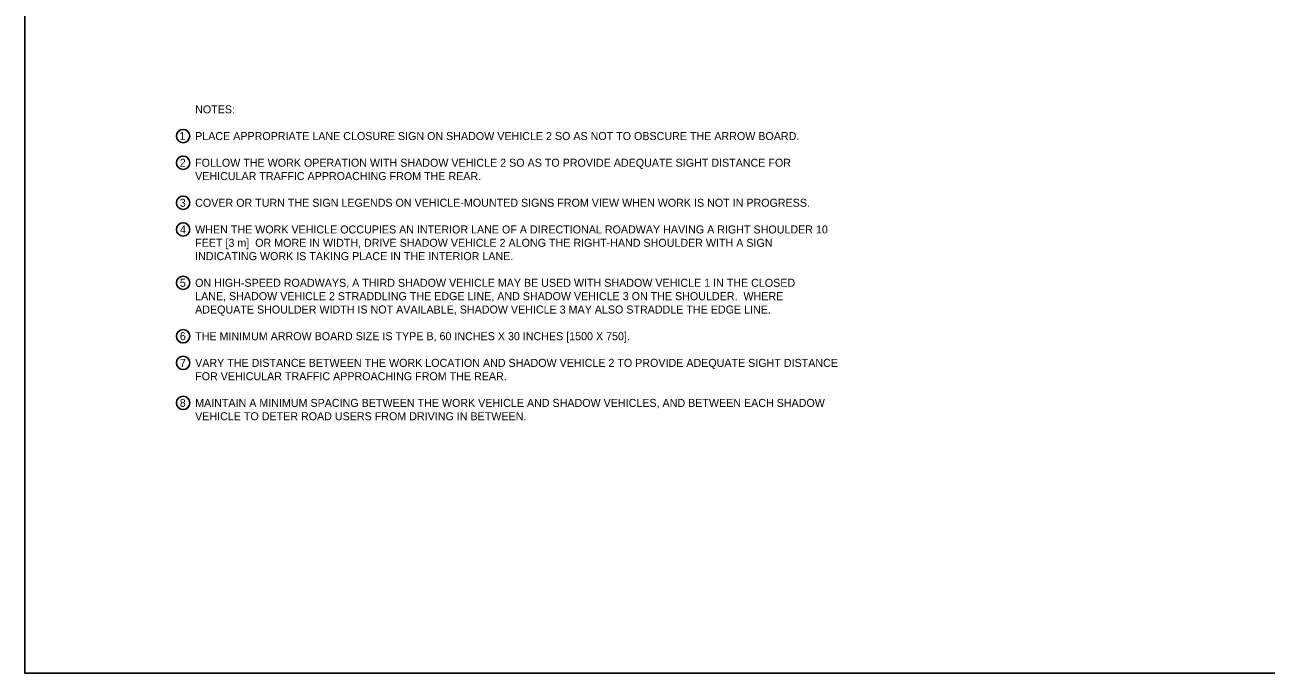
# Model space of a CAD drawing. Extents: x 49991.4 to 50021, y 49987.6 to 50011.4.
# Drawn here: x 49999.38 to 50008.69, y 49987.8 to 49992.66 of the extents above; entities that cross this region are included whole.
import ezdxf

# ---------------------------------------------------------------- set-up
doc = ezdxf.new("R2010")
doc.units = 0
doc.layers.add('Level 1', color=7, linetype='Continuous')
doc.layers.add('Level 2', color=7, linetype='Continuous')

msp = doc.modelspace()

# ---------------------------------------------------------------- linework, layer by layer
at = {"layer": 'Level 1'}
msp.add_lwpolyline([(49999.3835, 49998.9992), (50016.7501, 49998.9992), (50016.7501, 49987.7988), (49999.3835, 49987.7988)], close=True, dxfattribs=at)
at = {"layer": 'Level 2'}
for centre in [(50000.5703, 49991.8243), (50000.5703, 49991.6243), (50000.5703, 49991.3243), (50000.5703, 49991.1243), (50000.5703, 49990.7243), (50000.5703, 49990.3243), (50000.5703, 49990.1243), (50000.5703, 49989.8243)]:
    msp.add_circle(centre, 0.05, dxfattribs=at)

# ---------------------------------------------------------------- texts
for s, p in [('NOTES:', (50000.6603, 49991.9943)), ('1', (50000.5426, 49991.7943)), ('PLACE APPROPRIATE LANE CLOSURE SIGN ON SHADOW VEHICLE 2 SO AS NOT TO OBSCURE THE ARROW BOARD.', (50000.6603, 49991.7943)), ('2', (50000.5452, 49991.5943)), ('FOLLOW THE WORK OPERATION WITH SHADOW VEHICLE 2 SO AS TO PROVIDE ADEQUATE SIGHT DISTANCE FOR ', (50000.6603, 49991.5943)), ('VEHICULAR TRAFFIC APPROACHING FROM THE REAR.', (50000.6603, 49991.4943)), ('3', (50000.5451, 49991.2943)), ('COVER OR TURN THE SIGN LEGENDS ON VEHICLE-MOUNTED SIGNS FROM VIEW WHEN WORK IS NOT IN PROGRESS.', (50000.6603, 49991.2943)), ('4', (50000.5464, 49991.0943)), ('WHEN THE WORK VEHICLE OCCUPIES AN INTERIOR LANE OF A DIRECTIONAL ROADWAY HAVING A RIGHT SHOULDER 10 ', (50000.6603, 49991.0943)), ('FEET [3 m]  OR MORE IN WIDTH, DRIVE SHADOW VEHICLE 2 ALONG THE RIGHT-HAND SHOULDER WITH A SIGN ', (50000.6603, 49990.9943)), ('INDICATING WORK IS TAKING PLACE IN THE INTERIOR LANE.', (50000.6603, 49990.8943)), ('5', (50000.5454, 49990.6943)), ('ON HIGH-SPEED ROADWAYS, A THIRD SHADOW VEHICLE MAY BE USED WITH SHADOW VEHICLE 1 IN THE CLOSED ', (50000.6603, 49990.6943)), ('LANE, SHADOW VEHICLE 2 STRADDLING THE EDGE LINE, AND SHADOW VEHICLE 3 ON THE SHOULDER.  WHERE ', (50000.6603, 49990.5943)), ('ADEQUATE SHOULDER WIDTH IS NOT AVAILABLE, SHADOW VEHICLE 3 MAY ALSO STRADDLE THE EDGE LINE.', (50000.6603, 49990.4943)), ('6', (50000.5458, 49990.2943)), ('THE MINIMUM ARROW BOARD SIZE IS TYPE B, 60 INCHES X 30 INCHES [1500 X 750].', (50000.6603, 49990.2943)), ('7', (50000.5465, 49990.0943)), ('VARY THE DISTANCE BETWEEN THE WORK LOCATION AND SHADOW VEHICLE 2 TO PROVIDE ADEQUATE SIGHT DISTANCE ', (50000.6603, 49990.0943)), ('FOR VEHICULAR TRAFFIC APPROACHING FROM THE REAR.', (50000.6603, 49989.9943)), ('8', (50000.5453, 49989.7943)), ('MAINTAIN A MINIMUM SPACING BETWEEN THE WORK VEHICLE AND SHADOW VEHICLES, AND BETWEEN EACH SHADOW ', (50000.6603, 49989.7943)), ('VEHICLE TO DETER ROAD USERS FROM DRIVING IN BETWEEN.', (50000.6603, 49989.6943))]:
    msp.add_text(s, height=0.06, dxfattribs=at).set_placement(p)

doc.saveas('drawing.dxf')
